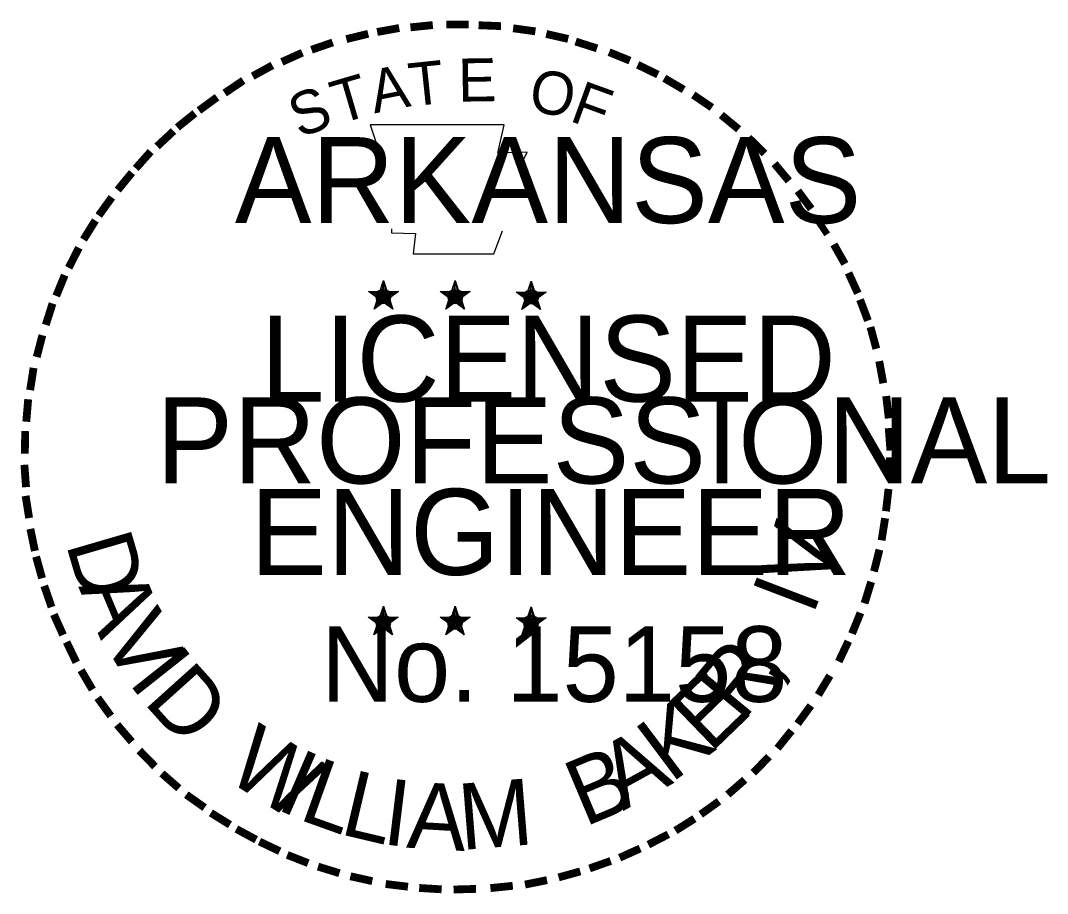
# Model space of a CAD drawing. Extents: x 96 to 721, y -177 to -41.
# Drawn here: x 709.06 to 721.38, y -66.97 to -56.51 of the extents above; entities that cross this region are included whole.
import ezdxf

# ---------------------------------------------------------------- set-up
doc = ezdxf.new("R2010")
doc.units = 0
doc.layers.add('R_Border PE', color=7, linetype='Continuous')

msp = doc.modelspace()

# ---------------------------------------------------------------- linework, layer by layer
at = {"layer": 'R_Border PE'}
for p, q in [((713.416, -59.626), (713.395, -59.756)), ((713.416, -59.814), (713.416, -59.626)), ((713.416, -59.626), (713.441, -59.755)), ((714.277, -59.626), (714.256, -59.756)), ((714.277, -59.814), (714.277, -59.626)), ((714.277, -59.626), (714.302, -59.755)), ((715.186, -59.632), (715.165, -59.762)), ((715.186, -59.82), (715.186, -59.632)), ((715.186, -59.632), (715.212, -59.761)), ((713.236, -59.757), (713.416, -59.814)), ((713.236, -59.757), (713.366, -59.78)), ((713.236, -59.757), (713.358, -59.82)), ((713.304, -59.967), (713.416, -59.814)), ((713.595, -59.757), (713.416, -59.814)), ((713.526, -59.967), (713.416, -59.814)), ((713.595, -59.757), (713.447, -59.782)), ((713.526, -59.967), (713.455, -59.817)), ((713.595, -59.757), (713.489, -59.81)), ((714.097, -59.757), (714.277, -59.814)), ((714.097, -59.757), (714.227, -59.78)), ((714.097, -59.757), (714.219, -59.82)), ((714.165, -59.967), (714.277, -59.814)), ((714.456, -59.757), (714.277, -59.814)), ((714.387, -59.967), (714.277, -59.814)), ((714.456, -59.757), (714.308, -59.782)), ((714.387, -59.967), (714.316, -59.817)), ((714.456, -59.757), (714.351, -59.81)), ((715.006, -59.763), (715.186, -59.82)), ((715.006, -59.763), (715.137, -59.786)), ((715.006, -59.763), (715.129, -59.826)), ((715.075, -59.974), (715.186, -59.82)), ((715.365, -59.763), (715.186, -59.82)), ((715.296, -59.974), (715.186, -59.82)), ((715.365, -59.763), (715.218, -59.788)), ((715.296, -59.974), (715.226, -59.824)), ((715.365, -59.763), (715.26, -59.816)), ((713.304, -59.967), (713.369, -59.842)), ((713.304, -59.967), (713.415, -59.855)), ((713.526, -59.967), (713.415, -59.857)), ((714.165, -59.967), (714.23, -59.842)), ((714.165, -59.967), (714.276, -59.855)), ((714.387, -59.967), (714.276, -59.857)), ((715.075, -59.974), (715.14, -59.848)), ((715.075, -59.974), (715.185, -59.862)), ((715.296, -59.974), (715.185, -59.863)), ((713.414, -63.531), (713.392, -63.661)), ((713.414, -63.719), (713.414, -63.531)), ((713.414, -63.531), (713.439, -63.66)), ((714.274, -63.531), (714.253, -63.661)), ((714.274, -63.719), (714.274, -63.531)), ((714.274, -63.531), (714.299, -63.66)), ((715.185, -63.536), (715.164, -63.666)), ((715.185, -63.724), (715.185, -63.536)), ((715.185, -63.536), (715.211, -63.665)), ((713.234, -63.662), (713.414, -63.719)), ((713.234, -63.662), (713.364, -63.685)), ((713.234, -63.662), (713.356, -63.725)), ((713.302, -63.872), (713.414, -63.719)), ((713.302, -63.872), (713.367, -63.746)), ((713.302, -63.872), (713.413, -63.76)), ((713.523, -63.872), (713.413, -63.762)), ((713.593, -63.662), (713.414, -63.719)), ((713.523, -63.872), (713.414, -63.719)), ((713.593, -63.662), (713.445, -63.687)), ((713.523, -63.872), (713.453, -63.722)), ((713.593, -63.662), (713.487, -63.714)), ((714.094, -63.662), (714.274, -63.719)), ((714.094, -63.662), (714.225, -63.685)), ((714.094, -63.662), (714.216, -63.725)), ((714.163, -63.872), (714.274, -63.719)), ((714.163, -63.872), (714.228, -63.746)), ((714.163, -63.872), (714.273, -63.76)), ((714.384, -63.872), (714.273, -63.762)), ((714.453, -63.662), (714.274, -63.719)), ((714.384, -63.872), (714.274, -63.719)), ((714.453, -63.662), (714.306, -63.687)), ((714.384, -63.872), (714.313, -63.722)), ((714.453, -63.662), (714.348, -63.714)), ((715.005, -63.667), (715.185, -63.724)), ((715.005, -63.667), (715.136, -63.69)), ((715.005, -63.667), (715.128, -63.73)), ((715.074, -63.877), (715.185, -63.724)), ((715.074, -63.877), (715.139, -63.752)), ((715.074, -63.877), (715.184, -63.765)), ((715.295, -63.877), (715.184, -63.767)), ((715.364, -63.667), (715.185, -63.724)), ((715.295, -63.877), (715.185, -63.724)), ((715.364, -63.667), (715.217, -63.692)), ((715.295, -63.877), (715.225, -63.727)), ((715.364, -63.667), (715.259, -63.72))]:
    msp.add_line(p, q, dxfattribs=at)
for points in [[(713.257, -57.757), (713.396, -58.184)], [(715.067, -58.233), (715.14, -58.086), (714.787, -58.099), (714.864, -57.757), (713.257, -57.757)], [(713.511, -59.007), (713.511, -59.052), (713.801, -59.061), (713.773, -59.305), (714.737, -59.305), (714.841, -59.029)], [(713.416, -59.626), (713.526, -59.967), (713.236, -59.757), (713.595, -59.757), (713.304, -59.967), (713.416, -59.626)], [(714.277, -59.626), (714.387, -59.967), (714.097, -59.757), (714.456, -59.757), (714.165, -59.967), (714.277, -59.626)], [(715.186, -59.632), (715.296, -59.974), (715.006, -59.763), (715.365, -59.763), (715.075, -59.974), (715.186, -59.632)], [(713.414, -63.531), (713.523, -63.872), (713.234, -63.662), (713.593, -63.662), (713.302, -63.872), (713.414, -63.531)], [(714.274, -63.531), (714.384, -63.872), (714.094, -63.662), (714.453, -63.662), (714.163, -63.872), (714.274, -63.531)], [(715.185, -63.536), (715.295, -63.877), (715.005, -63.667), (715.364, -63.667), (715.074, -63.877), (715.185, -63.536)]]:
    msp.add_lwpolyline(points, dxfattribs=at)
for centre, radius in [((713.415, -59.815), 0.0888), ((713.415, -59.815), 0.0745), ((713.415, -59.815), 0.0597), ((713.415, -59.815), 0.0511), ((713.415, -59.815), 0.0385), ((713.415, -59.815), 0.0255), ((713.415, -59.815), 0.0153), ((714.276, -59.815), 0.0888), ((714.276, -59.815), 0.0745), ((714.276, -59.815), 0.0597), ((714.276, -59.815), 0.0511), ((714.276, -59.815), 0.0385), ((714.276, -59.815), 0.0255), ((714.276, -59.815), 0.0153), ((715.186, -59.821), 0.0888), ((715.186, -59.821), 0.0745), ((715.186, -59.821), 0.0597), ((715.186, -59.821), 0.0511), ((715.186, -59.821), 0.0385), ((715.186, -59.821), 0.0255), ((715.186, -59.821), 0.0153), ((713.413, -63.719), 0.0888), ((713.413, -63.719), 0.0745), ((714.274, -63.719), 0.0888), ((714.274, -63.719), 0.0745), ((715.185, -63.725), 0.0888), ((713.413, -63.719), 0.0597), ((713.413, -63.719), 0.0511), ((713.413, -63.719), 0.0385), ((713.413, -63.719), 0.0255), ((713.413, -63.719), 0.0153), ((714.274, -63.719), 0.0597), ((714.274, -63.719), 0.0511), ((714.274, -63.719), 0.0385), ((714.274, -63.719), 0.0255), ((714.274, -63.719), 0.0153), ((715.185, -63.725), 0.0745), ((715.185, -63.725), 0.0597), ((715.185, -63.725), 0.0511), ((715.185, -63.725), 0.0385), ((715.185, -63.725), 0.0255), ((715.185, -63.725), 0.0153)]:
    msp.add_circle(centre, radius, dxfattribs=at)

# ---------------------------------------------------------------- texts
for s, height, rotation, p in [('-', 0.825, 13.6302, (712.998, -57.052)), ('-', 0.825, 10.2193, (713.348, -56.968)), ('-', 0.825, 5.8968, (713.723, -56.912)), ('-', 0.825, 0.1862, (714.121, -56.875)), ('-', 0.825, 357.743, (714.494, -56.881)), ('-', 0.825, 352.1617, (714.878, -56.91)), ('-', 0.825, 347.2049, (715.249, -56.969)), ('-', 0.825, 19.1761, (712.611, -57.176)), ('-', 0.825, 342.3362, (715.576, -57.049)), ('-', 0.825, 24.3072, (712.284, -57.315)), ('-', 0.825, 337.8551, (715.955, -57.164)), ('T', 0.516, 6.0228, (713.744, -57.538)), ('E', 0.516, 0.8323, (714.313, -57.481)), ('-', 0.825, 334.1211, (716.28, -57.304)), ('-', 0.825, 28.7918, (711.958, -57.478)), ('A', 0.516, 11.2132, (713.306, -57.623)), ('O', 0.516, 350.4515, (715.14, -57.589)), ('-', 0.825, 34.0636, (711.65, -57.669)), ('T', 0.516, 16.4036, (712.88, -57.753)), ('F', 0.516, 340.0707, (715.632, -57.707)), ('-', 0.825, 329.6409, (716.579, -57.45)), ('S', 0.516, 21.594, (712.409, -57.923)), ('-', 0.825, 325.8627, (716.91, -57.636)), ('-', 0.825, 36.2317, (711.352, -57.873)), ('-', 0.825, 38.9507, (711.107, -58.068)), ('-', 0.825, 320.5297, (717.225, -57.855)), ('-', 0.825, 42.9622, (710.883, -58.283)), ('-', 0.825, 315.5786, (717.534, -58.107)), ('-', 0.825, 48.4231, (710.652, -58.529)), ('-', 0.825, 309.8797, (717.827, -58.391)), ('-', 0.825, 50.6142, (710.445, -58.78)), ('-', 0.825, 306.6522, (718.098, -58.701)), ('-', 0.825, 54.2325, (710.232, -59.072)), ('-', 0.825, 58.0706, (710.064, -59.344)), ('-', 0.722, 303.6753, (718.349, -58.994)), ('-', 0.825, 62.8713, (709.903, -59.661)), ('-', 0.825, 299.6684, (718.513, -59.307)), ('-', 0.825, 67.7743, (709.769, -59.976)), ('-', 0.825, 294.6628, (718.68, -59.622)), ('-', 0.825, 72.3945, (709.656, -60.3)), ('-', 0.825, 290.5728, (718.813, -59.92)), ('-', 0.825, 285.1233, (718.933, -60.219)), ('-', 0.825, 75.461, (709.555, -60.669)), ('-', 0.825, 81.2013, (709.487, -61.036)), ('-', 0.825, 280.5493, (719.036, -60.602)), ('-', 0.825, 85.1863, (709.447, -61.393)), ('-', 0.825, 276.5962, (719.12, -60.998)), ('-', 0.825, 274.3301, (719.151, -61.37)), ('-', 0.825, 89.0622, (709.434, -61.754)), ('-', 0.825, 269.9407, (719.168, -61.696)), ('-', 0.825, 94.1959, (709.452, -62.128)), ('-', 0.825, 263.5172, (719.159, -62.039)), ('-', 0.825, 98.9479, (709.49, -62.472)), ('V', 0.794, 72.6573, (718.676, -63.377)), ('-', 0.825, 260.9953, (719.122, -62.376)), ('-', 0.825, 101.7149, (709.559, -62.85)), ('D', 0.794, 286.2848, (709.605, -62.778)), ('-', 0.825, 255.7626, (719.065, -62.726)), ('-', 0.825, 105.4578, (709.643, -63.157)), ('-', 0.825, 109.0874, (709.754, -63.482)), ('A', 0.794, 292.7835, (709.756, -63.295)), ('I', 0.794, 69.0301, (718.561, -63.655)), ('-', 0.825, 252.8681, (718.972, -63.097)), ('V', 0.794, 300.7936, (710.021, -63.903)), ('-', 0.825, 114.0643, (709.885, -63.789)), ('-', 0.825, 247.8887, (718.857, -63.444)), ('-', 0.825, 115.7289, (710.042, -64.108)), ('R', 0.794, 50.3651, (717.71, -64.938)), ('-', 0.825, 244.6197, (718.722, -63.769)), ('I', 0.794, 308.3502, (710.346, -64.438)), ('D', 0.794, 311.9774, (710.527, -64.678)), (',', 0.794, 57.4684, (718.083, -64.483)), ('-', 0.825, 120.4471, (710.226, -64.41)), ('E', 0.794, 44.0175, (717.332, -65.303)), ('-', 0.825, 239.0712, (718.519, -64.156)), ('-', 0.825, 125.8934, (710.434, -64.699)), ('K', 0.794, 36.9143, (716.863, -65.659)), ('-', 0.825, 233.8452, (718.311, -64.493)), ('-', 0.825, 130.7181, (710.672, -64.984)), ('W', 0.794, 328.0731, (711.496, -65.589)), ('-', 0.825, 231.2538, (718.09, -64.785)), ('A', 0.794, 28.9042, (716.287, -65.987)), ('-', 0.825, 134.2238, (710.939, -65.265)), ('B', 0.794, 22.8589, (715.825, -66.18)), ('I', 0.794, 336.6877, (712.108, -65.954)), ('L', 0.794, 340.3149, (712.381, -66.08)), ('-', 0.825, 225.7653, (717.843, -65.076)), ('-', 0.825, 138.9338, (711.209, -65.504)), ('L', 0.794, 346.6625, (712.876, -66.258)), ('I', 0.794, 353.0101, (713.387, -66.38)), ('M', 0.794, 4.6473, (714.347, -66.454)), ('-', 0.825, 221.0851, (717.574, -65.338)), ('A', 0.794, 356.6373, (713.684, -66.424)), ('-', 0.825, 144.6463, (711.496, -65.713)), ('-', 0.825, 215.7363, (717.291, -65.581)), ('-', 0.825, 148.0898, (711.785, -65.905)), ('-', 0.825, 212.2491, (717.015, -65.781)), ('-', 0.825, 151.5704, (712.084, -66.072)), ('-', 0.825, 207.3568, (716.727, -65.959)), ('-', 0.825, 154.6002, (712.353, -66.2)), ('-', 0.825, 158.5612, (712.675, -66.331)), ('-', 0.825, 204.2516, (716.406, -66.124)), ('-', 0.825, 199.4643, (716.08, -66.267)), ('-', 0.825, 162.7983, (713.029, -66.441)), ('-', 0.825, 167.5555, (713.398, -66.525)), ('-', 0.825, 195.4743, (715.737, -66.389)), ('-', 0.825, 173.1155, (713.796, -66.582)), ('-', 0.825, 185.8167, (714.982, -66.56)), ('-', 0.825, 191.2858, (715.362, -66.492)), ('-', 0.825, 176.5183, (714.181, -66.609)), ('-', 0.825, 181.5918, (714.565, -66.599))]:
    msp.add_text(s, height=height, rotation=rotation, dxfattribs=at).set_placement(p)
for s, height, p in [('ARKANSAS', 1.0312, (711.634, -58.937)), ('LICENSED', 1.0312, (711.942, -61.076)), ('PROFESSIONAL', 1.03125, (710.693, -62.058)), ('ENGINEER', 1.0312, (711.82, -63.154)), ('No. 15158', 0.906, (712.667, -64.676)), ('AAMU', 0.0000103, (714.24, -66.457))]:
    msp.add_text(s, height=height, dxfattribs=at).set_placement(p)

doc.saveas('drawing.dxf')
